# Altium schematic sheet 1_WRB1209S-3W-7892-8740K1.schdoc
size 289 x 200 mm; Name: default297x210; Symbol: default297x210; Device: default297x210; Date: 2025.07.09; Rev: V1.1; Size: "A4"; Id: /; File: WRB1209S-3W-7892-8740K1; Sheet: /; @Page No: 1; @Page Count: 1; @Schematic Name: WRB1209S-3W-7892-8740K1; @Project Name: 反激隔离电源-WRB1209S-3W-7892-8740K1; @Board Name: WRB1209S-3W-7892-8740K1; @Update Date: 2025-07-01; @Create Time: 15:51:47; @Update Time: 15:51:55; @Page Name: WRB1209S-3W-7892-8740K1; @Create Date: 2025-07-01
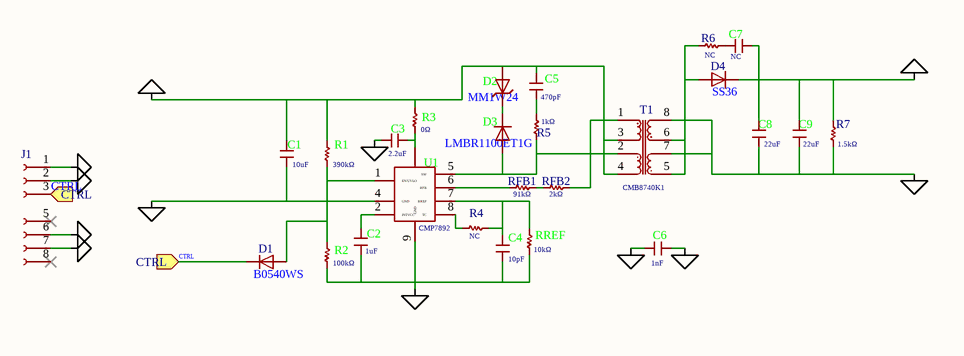
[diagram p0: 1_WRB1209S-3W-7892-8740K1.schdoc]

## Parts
C1  10uF  [C0805]
C2  1uF  [C0603]
C3  2.2uF  [C0603]
C4  10pF  [C0603]
C5  470pF  [C0603]
C6  1nF  [C1206]
C7  NC  [C0603]
C8  22uF  [C0805]
C9  22uF  [C0805]
D1  B0540WS  [SOD-323_L1.8-W1.3-LS2.5-RD]
D2  MM1W24  [SOD-123_L2.8-W1.8-LS3.9-FD]
D3  LMBR1100ET1G  [SOD-323HE_L1.9-W1.3-LS2.5-RD]
D4  SS36  [SMA_L4.3-W2.6-LS5.2-RD]
J1  Coileasy_Conn_01x07_1  [coileasy:PinHeader_01x07_1_P2.54mm_Vertical]  (value not drawn)
R1  390kΩ  [R0603]
R2  100kΩ  [R0603]
R3  0Ω  [R0603]
R4  NC  [R0603]
R5  1kΩ  [R0603]
R6  NC  [R0603]
R7  1.5kΩ  [R0805]
RFB1  91kΩ  [R0603]
RFB2  2kΩ  [R0603]
RREF  10kΩ  [R0603]
T1  CMB8740K1  [coileasy:SMD-8P, 11.55x9.6, ER9.5 4+4]
U1  CMP7892  [coileasy:ESOP-8]

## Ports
CTRL (in)

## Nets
GND1: C1.2 C2.1 C3.2 C4.1 C6.2 J1.1 R2.1 RREF.1 U1.4(GND) U1.9(GND)
GND2: C6.1 C8.2 C9.2 J1.7 R7.2 T1.7 T1.8
VIN: C1.1 C5.2 D2.2 J1.2 R1.2 R3.2 T1.3 T1.4
VO: C7.2 C8.1 C9.1 D4.1 J1.6 R7.1
CTRL: D1.1 J1.3 ; port CTRL
NetC2_2: C2.2 U1.2(INTVCC)
NetC3_1: C3.1 R3.1 U1.3
NetC4_2: C4.2 R4.1 RREF.2 U1.7(RREF)
NetC5_1: C5.1 R5.1
NetC7_1: C7.1 R6.1
NetD1_2: D1.2 R1.1 R2.2 U1.1(EN/UVLO)
NetD2_1: D2.1 D3.1
NetD3_2: D3.2 R5.2 RFB2.1 T1.1 T1.2 U1.5(SW)
NetD4_2: D4.2 R6.2 T1.5 T1.6
NetR4_2: R4.2 U1.8(TC)
NetRFB1_1: RFB1.1 RFB2.2
NetRFB1_2: RFB1.2 U1.6(RFB)

Not connected (* = marked no-connect by the designer): J1 5* 8*

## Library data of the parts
C1 = CGA0805X5R106K350MT: Manufacturer: HRE(芯声); Symbol: MY_C; Add into BOM: yes; Tolerance: ±10%; Voltage Rating: 35V; Temperature Coefficient: X5R
C2 = 0603B105K250NT: Manufacturer: FH(风华); Symbol: MY_C; Add into BOM: yes; Tolerance: ±10%; Voltage Rating: 25V; Temperature Coefficient: X7R
C3 = CGA0603X5R225K350JT: Manufacturer: HRE(芯声); Symbol: MY_C; Add into BOM: yes; Tolerance: ±10%; Voltage Rating: 35V; Temperature Coefficient: X5R
C4 = CC0603JRNPO9BN100: Manufacturer: YAGEO(国巨); Symbol: C; Add into BOM: yes; Tolerance: ±5%; Voltage Rated: 50V; Temperature Coefficient: NP0
C5 = CC0603KRX7R9BB471: Manufacturer: YAGEO(国巨); Symbol: C; Add into BOM: yes; Tolerance: ±10%; Voltage Rated: 50V; Temperature Coefficient: X7R
C6 = CC1206KKX7RDBB102: Manufacturer: YAGEO(国巨); Symbol: MY_C; Add into BOM: yes; Tolerance: ±10%; Voltage Rated: 2kV; Temperature Coefficient: X7R
C7 = C: Add into BOM: yes; Tolerance: ±5%
C8 C9 = 0805X226M250NT: Manufacturer: FH(风华); Symbol: MY_C; Add into BOM: yes; Tolerance: ±20%; Voltage Rating: 25V; Temperature Coefficient: X5R
D1 = B0540WS_C475613: Manufacturer: SHIKUES(时科); Symbol: Coileasy library_D; Add into BOM: yes; Diode Configuration: 独立式; Forward Voltage (Vf@If): 600mV@200mA; Reverse Voltage (Vr): 40V; Average Rectified Current (Io): 350mA; Reverse Leakage Current (Ir): 5uA@30V
D2 = MM1W24_C22395531: Manufacturer: 宏迦橙; Symbol: My library_D_Zener; Add into BOM: yes; Diode Configuration: 独立式; Zener Voltage (Nom): 24V; Reverse Leakage Current (Ir): 5uA@18V; Zener Voltage (Range): 22.8V~26V; Power Dissipation: 1W; Zener Impedance (Zzt): 25Ω
D3 = LMBR1100ET1G_C20622202: Manufacturer: DOWO(东沃); Symbol: My library_DSS210; Add into BOM: yes; Voltage - DC Reverse(Vr): 100V; Current - Rectified: 1A
D4 = SS36_C16015: Manufacturer: MDD(辰达半导体); Symbol: My library_DSS210; Add into BOM: yes; Diode Configuration: 独立式; Forward Voltage (Vf@If): 700mV@3A; Reverse Voltage (Vr): 60V; Rectified Current: 3A; Reverse Leakage Current (Ir): 500uA@60V
J1 = Coileasy_Conn_01x07_1: ki_fp_filters: Connector*:*_1x??_*; Add into BOM: yes
R1 = RC0603FR-07390KL: Manufacturer: YAGEO(国巨); Symbol: R; Add into BOM: yes; Tolerance: ±1%; Power(Watts): 100mW; Overload Voltage (Max): 75V; Temperature Coefficient: ±100ppm/℃
R2 = RC0603FR-07100KL: Manufacturer: YAGEO(国巨); Symbol: R; Add into BOM: yes; Tolerance: ±1%; Power(Watts): 100mW; Overload Voltage (Max): 75V; Temperature Coefficient: ±100ppm/℃
R3 = RC0603FR-070RL: Manufacturer: YAGEO(国巨); Symbol: R; Add into BOM: yes; Tolerance: ±1%; Power(Watts): 100mW; Voltage-Supply(Max): 75V
R4 R6 = R: Add into BOM: yes; Tolerance: ±1%; Power(Watts): 100mW; Overload Voltage (Max): 75V; Temperature Coefficient: ±100ppm/℃
R5 = RC0603FR-071KL: Manufacturer: YAGEO(国巨); Symbol: R; Add into BOM: yes; Tolerance: ±1%; Power(Watts): 100mW; Voltage-Supply(Max): 75V; Temperature Coefficient: ±100ppm/℃
R7 = RC0805FR-071K5L: Manufacturer: YAGEO(国巨); Symbol: R; Add into BOM: yes; Tolerance: ±1%; Power(Watts): 125mW; Overload Voltage (Max): 150V; Temperature Coefficient: ±100ppm/℃
RFB1 = RC0603FR-0791KL: Manufacturer: YAGEO(国巨); Symbol: R; Add into BOM: yes; Tolerance: ±1%; Power(Watts): 100mW; Overload Voltage (Max): 75V; Temperature Coefficient: ±100ppm/℃
RFB2 = RC0603FR-072KL: Manufacturer: YAGEO(国巨); Symbol: R; Add into BOM: yes; Tolerance: ±1%; Power(Watts): 100mW; Voltage-Supply(Max): 75V; Temperature Coefficient: ±100ppm/℃
RREF = RC0603FR-0710KL: Manufacturer: YAGEO(国巨); Symbol: R; Add into BOM: yes; Tolerance: ±1%; Power(Watts): 100mW; Overload Voltage (Max): 75V; Temperature Coefficient: ±100ppm/℃
T1 = CMB8740K1: Add into BOM: yes
U1 = CMP7892: Add into BOM: yes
